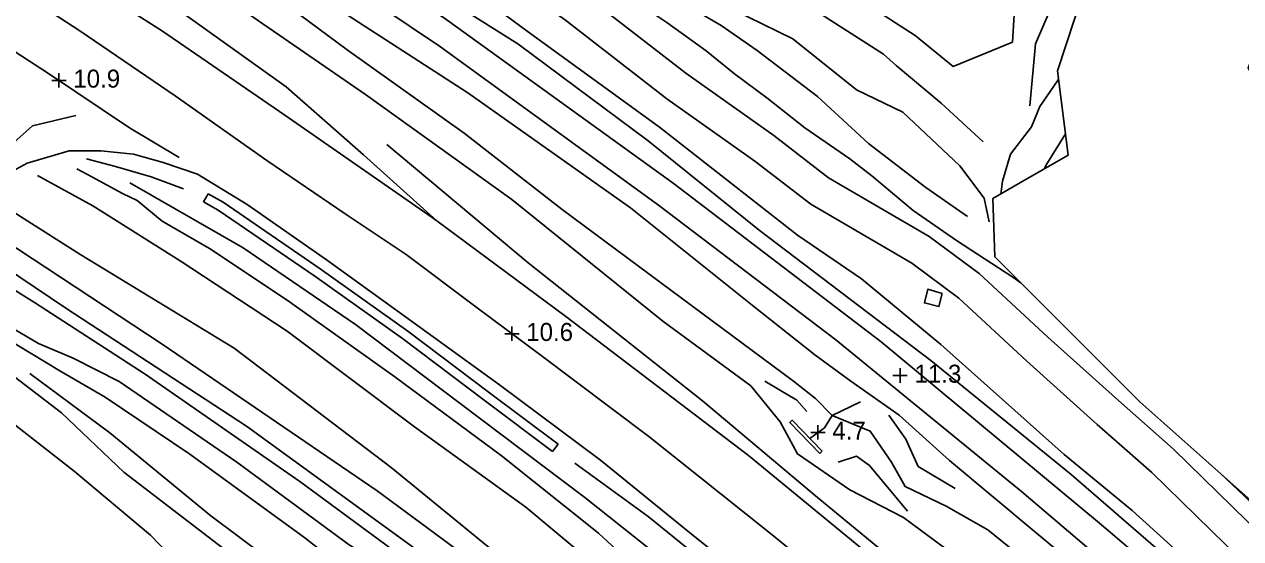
# Model space of a CAD drawing. Extents: x 2316231 to 2323598, y 363169 to 371906.
# Drawn here: x 2320501.8 to 2320840, y 365756.1 to 365899 of the extents above; entities that cross this region are included whole.
import ezdxf

# ---------------------------------------------------------------- set-up
doc = ezdxf.new("R2010")
doc.units = 0
for name, color, linetype in [('RD_DTM_BkLn1', 7, 'Continuous'), ('RD_DTM_Holes', 7, 'Continuous'), ('RD_DTM_Void', 7, 'Continuous'), ('RD_EX_H2O', 7, 'Continuous'), ('RD_EX_Road', 7, 'Continuous')]:
    doc.layers.add(name, color=color, linetype=linetype)

msp = doc.modelspace()

# ---------------------------------------------------------------- linework, layer by layer
at = {"layer": 'RD_DTM_BkLn1'}
msp.add_line((2320531.022, 365870.231), (2320544.889, 365862.035), dxfattribs=at)
for points in [[(2320183.14, 366148.693), (2320239.09, 366117.639), (2320296.494, 366085.739), (2320349.802, 366055.132), (2320405.378, 366025.418), (2320448.083, 365999.362), (2320490.768, 365974.618), (2320559.324, 365931.873), (2320617.279, 365892.959), (2320678.148, 365848.809), (2320727.47, 365811.314), (2320779.04, 365769.194), (2320836.996, 365719.869), (2320889.686, 365671.382)], [(2320125.425, 366145.994), (2320161.294, 366129.015), (2320184.806, 366118.194), (2320219.268, 366097.334), (2320257.75, 366078.61), (2320301.401, 366053.593), (2320339.6, 366032.049), (2320388.854, 366006.136), (2320433.491, 365980.54), (2320471.094, 365961.437), (2320509.936, 365935.57), (2320558.33, 365906.04), (2320596.656, 365879.53), (2320637.36, 365850.344), (2320679.307, 365816.521), (2320703.841, 365798.525), (2320711.978, 365788.521), (2320716.795, 365779.622), (2320731.36, 365769.609), (2320746.226, 365761.92), (2320773.664, 365741.714), (2320802.121, 365716.946), (2320848.849, 365676.056), (2320875.469, 365654.227)], [(2320182.737, 366143.817), (2320231.045, 366116.001), (2320278.866, 366087.979), (2320328.405, 366059.321), (2320373.611, 366034.853), (2320417.281, 366010.392), (2320460.243, 365986.01), (2320498.805, 365963.232), (2320547.113, 365932.568), (2320590.276, 365902.488), (2320625.131, 365879.992), (2320670.35, 365847.996), (2320704.214, 365820.962), (2320721.604, 365807.145), (2320731.665, 365799.894), (2320745.055, 365790.38), (2320759.08, 365777.797), (2320794.333, 365748.347), (2320828.782, 365718.919), (2320859.537, 365690.73), (2320885.477, 365666.303)], [(2320232.419, 366129.527), (2320276.765, 366104.361), (2320326.97, 366076.072), (2320377.845, 366047.504), (2320438.873, 366013.35), (2320491.432, 365981.475), (2320553.439, 365943.338), (2320618.359, 365900.899), (2320682.218, 365854.928), (2320740.085, 365810.827), (2320800.745, 365760.357), (2320857.803, 365711.976), (2320894.516, 365677.21)], [(2320320.221, 366098.87), (2320343.73, 366084.834), (2320356.505, 366077.219), (2320384.555, 366059.676), (2320419.447, 366040.181), (2320447.866, 366021.901), (2320471.868, 366008.615), (2320488.936, 365996.515), (2320514.303, 365982.74), (2320529.316, 365972.626), (2320554.954, 365955.917), (2320587.739, 365935.149), (2320612.576, 365918.662), (2320641.664, 365897.147), (2320678.381, 365870.456), (2320716.77, 365840.459), (2320734.571, 365828.326), (2320756.632, 365810.066), (2320790.938, 365779.493), (2320809.818, 365763.92), (2320848.173, 365729.232), (2320863.138, 365716.2), (2320899.36, 365685.757), (2320900.62, 365684.576)], [(2320315.308, 366088.614), (2320345.863, 366070.993), (2320387.782, 366047.357), (2320430.265, 366024.388), (2320470.415, 366003.883), (2320504.878, 365981.214), (2320529.854, 365965.458), (2320578.485, 365933.231), (2320618.03, 365906.824), (2320639.032, 365893.635), (2320675.308, 365866.642), (2320706.175, 365841.844), (2320753.882, 365805.574), (2320792.936, 365773.891), (2320828.235, 365743.377), (2320879.989, 365695.168), (2320896.418, 365679.505)], [(2320768.392, 365866.361), (2320756.708, 365877.083), (2320744.252, 365887.566), (2320740.687, 365890.766), (2320726.055, 365900.142), (2320710.288, 365910.418), (2320684.057, 365924.05), (2320656.815, 365943.875), (2320639.525, 365956.203), (2320622.508, 365966.719), (2320606.645, 365977.824), (2320598.246, 365982.88), (2320591.282, 365990.258), (2320583.747, 365995.374), (2320568.719, 366003.277), (2320549.326, 366013.752), (2320528.668, 366027.008), (2320512.279, 366039.596), (2320486.864, 366058.051)], [(2320499.898, 366035.117), (2320518.783, 366024.708), (2320539.775, 366013.575), (2320551, 366005.825), (2320566.423, 365997.349), (2320574.595, 365991.103), (2320579.668, 365988.57), (2320584.457, 365982.129), (2320591.38, 365978.131), (2320601.704, 365971.102), (2320609.064, 365967.122), (2320630.418, 365948.02), (2320645.146, 365939.719), (2320660.769, 365929.255), (2320670.56, 365922.043), (2320694.612, 365905.223), (2320715.486, 365895.037), (2320733.213, 365880.79), (2320746.065, 365874.627), (2320761.94, 365859.741), (2320768.707, 365850.734), (2320770.054, 365844.1)], [(2320764.035, 365845.663), (2320752.506, 365853.724), (2320736.562, 365865.941), (2320722.342, 365878.987), (2320705.589, 365891.721), (2320695.572, 365898.724), (2320680.484, 365907.597), (2320662.741, 365921.455), (2320651.647, 365927.407), (2320628.585, 365944.084), (2320610.724, 365955.154), (2320600.628, 365963.434), (2320580.454, 365977.629), (2320563.696, 365987.078), (2320549.277, 365995.494), (2320537.141, 366003.22), (2320521.388, 366014.595), (2320497.7, 366028.456)], [(2320778.851, 365827.229), (2320776.707, 365828.796), (2320760.961, 365838.918), (2320748.976, 365847.328), (2320737.491, 365856.96), (2320731.391, 365861.609), (2320718.843, 365870.309), (2320708.251, 365878.642), (2320699.269, 365885.241), (2320691.419, 365891.649), (2320680.432, 365899.55), (2320665.759, 365909.434), (2320648.973, 365921.401), (2320634.153, 365930.933), (2320610.18, 365947.515), (2320596.411, 365956.939), (2320573.742, 365971.933), (2320553.973, 365984.422), (2320539.048, 365994.014), (2320520.799, 366003.328), (2320499.315, 366016.701)], [(2320531.022, 365870.231), (2320508.52, 365885.4), (2320485.858, 365899.969), (2320466.913, 365913.192), (2320446.479, 365926.41), (2320433.746, 365934.556)], [(2320543.695, 365879.161), (2320517.247, 365897.216), (2320496.287, 365910.936), (2320471.832, 365924.913)], [(2320800.011, 365919.344), (2320788.86, 365907.244), (2320783.018, 365893.597), (2320781.363, 365876.411)], [(2320789.378, 365883.84), (2320789.071, 365883.323), (2320784.137, 365876.199), (2320781.833, 365870.52), (2320776.044, 365862.969), (2320773.799, 365855.457), (2320773.336, 365851.874)], [(2320855.357, 365629.958), (2320845.868, 365638.904), (2320819.287, 365663.389), (2320796.672, 365683.748), (2320768.394, 365708.644), (2320741.53, 365731.29), (2320709.31, 365757.523), (2320675.444, 365784.438), (2320645.131, 365807.256), (2320627.321, 365820.5), (2320607.968, 365835.099), (2320591.031, 365846.394), (2320569.199, 365861.189), (2320543.695, 365879.161)], [(2320516.092, 365873.737), (2320504.049, 365870.79), (2320492.709, 365860.72), (2320483.032, 365850.358), (2320472.873, 365837.355)], [(2320602.629, 365865.677), (2320641.904, 365832.75), (2320690.389, 365794.379), (2320722.377, 365767.546), (2320771.111, 365727.387), (2320832.413, 365675.302), (2320868.558, 365645.887)], [(2320546.046, 365853.297), (2320537.071, 365856.611), (2320527.144, 365859.511), (2320519.123, 365861.643)], [(2320505.475, 365856.979), (2320520.864, 365848.587), (2320545.172, 365833.324), (2320574.899, 365813.74), (2320610.258, 365787.16), (2320641.215, 365764.842), (2320658.117, 365750.723), (2320662.317, 365742.611), (2320663.086, 365735.015), (2320670.708, 365727.381), (2320681.36, 365723.951), (2320702.529, 365710.89), (2320738.215, 365682.049), (2320755.731, 365664.117), (2320790.277, 365635.787), (2320826.19, 365604.332), (2320830.311, 365599.735)], [(2320531.154, 365854.994), (2320562.66, 365836.912), (2320593.866, 365815.631), (2320622.996, 365793.667), (2320657.616, 365767.534), (2320674.76, 365753.896), (2320691.644, 365742.188), (2320712.309, 365725.73), (2320742.067, 365699.137), (2320765.35, 365677.399), (2320794.487, 365652.244), (2320830.03, 365620.462), (2320839.699, 365611.064)], [(2320494.756, 365849.313), (2320517.539, 365834.967), (2320560.151, 365809.006), (2320603.795, 365775.848), (2320645.456, 365741.875), (2320664.804, 365725.847), (2320689.325, 365706.764), (2320719.517, 365681.82), (2320774.711, 365633.699), (2320816.181, 365591.988), (2320820.585, 365587.999)], [(2320487.964, 365837.237), (2320513.325, 365820.129), (2320563.533, 365787.35), (2320615.078, 365749.886), (2320667.434, 365710.191), (2320715.063, 365670.543), (2320756.33, 365633.36), (2320801.65, 365593.339), (2320814.522, 365580.683)], [(2320495.801, 365839.314), (2320540.146, 365810.177), (2320599.875, 365769.409), (2320648.098, 365733.83), (2320703.015, 365690.061), (2320756.957, 365642.96), (2320808.871, 365595.211), (2320818.714, 365585.741)], [(2320485.487, 365833.622), (2320504.647, 365821.714), (2320535.41, 365801.833), (2320578.386, 365771.968), (2320617.431, 365743.287), (2320659.726, 365709.98), (2320694.071, 365682.621), (2320730.364, 365652.213), (2320749.321, 365632.325), (2320781.055, 365603.107), (2320810.117, 365575.367)], [(2320475.372, 365817.646), (2320481.696, 365821.632), (2320490.565, 365819.23), (2320505.711, 365810.344), (2320515.374, 365806.23), (2320528.128, 365799.749), (2320560.904, 365777.338), (2320592.16, 365754.331), (2320614.238, 365740.301), (2320637.32, 365721.378), (2320642.869, 365714.337), (2320644.444, 365714.613)], [(2320434.813, 365750.977), (2320450.725, 365774.25), (2320465.315, 365792.894), (2320477.836, 365808.657), (2320485.329, 365810.561), (2320491.873, 365806.533), (2320512.09, 365791.073), (2320529.506, 365774.584), (2320568.018, 365744.987)], [(2320503.28, 365801.995), (2320525.612, 365785.54), (2320553.699, 365762.395), (2320584.774, 365739.166), (2320608.674, 365720.434), (2320622.584, 365709.046), (2320627.658, 365704.681), (2320620.473, 365687.552), (2320621.449, 365684.302)], [(2320719.4, 365791.407), (2320716.485, 365794.634), (2320714.996, 365795.539), (2320707.711, 365799.884)], [(2320742.218, 365790.368), (2320746.923, 365783.774), (2320750.303, 365776.169), (2320760.614, 365769.99)], [(2320654.91, 365777.105), (2320675.289, 365762.269), (2320700.245, 365742.034), (2320733.027, 365713.442)], [(2320728.136, 365777.366), (2320733.178, 365778.969), (2320736.786, 365776.384), (2320747.348, 365763.726)], [(2320891.97, 365722.614), (2320872.135, 365739.369), (2320854.837, 365753.86), (2320840.972, 365767.941), (2320834.306, 365774.288)]]:
    msp.add_lwpolyline(points, dxfattribs=at)
at = {"layer": 'RD_DTM_Holes'}
msp.add_lwpolyline([(2320869.591, 365742.934), (2320812.024, 365794.086), (2320771.624, 365834.449), (2320771.151, 365850.598), (2320778.817, 365855.076), (2320792.1, 365862.675), (2320789.082, 365886.135), (2320803.561, 365930.13), (2320827.143, 365964.83), (2320847.36, 365988.415), (2320856.368, 365987.689), (2320864.974, 365979.309), (2320883.365, 365970.076), (2320884.869, 365948.36), (2320851.417, 365908.749), (2320842.106, 365886.919), (2320849.793, 365872.134), (2320872.565, 365844.447), (2320903.42, 365831.029), (2320938.866, 365827.634), (2320967.2, 365821.516), (2320982.278, 365798.58), (2320978.958, 365776.734), (2320986.815, 365765.174)], dxfattribs=at)
at = {"layer": 'RD_DTM_Void'}
for p, q in [((2320511.419, 365881.446), (2320511.419, 365885.446)), ((2320509.419, 365883.446), (2320513.419, 365883.446)), ((2320637.367, 365811.03), (2320637.367, 365815.03)), ((2320635.367, 365813.03), (2320639.367, 365813.03)), ((2320745.333, 365799.432), (2320745.333, 365803.432)), ((2320743.333, 365801.432), (2320747.333, 365801.432)), ((2320722.479, 365783.613), (2320722.479, 365787.613)), ((2320720.479, 365785.613), (2320724.479, 365785.613))]:
    msp.add_line(p, q, dxfattribs=at)
at = {"layer": 'RD_EX_H2O'}
msp.add_line((2320734.346, 365794.154), (2320726.404, 365790.317), dxfattribs=at)
for points in [[(2320221.567, 366109.612), (2320246.01, 366095.432), (2320275.628, 366082.36), (2320308.416, 366062.762), (2320348.828, 366042.465), (2320390.844, 366019.006), (2320428.93, 365996.954), (2320463.386, 365976.566), (2320497.874, 365954.051), (2320534.331, 365932.126), (2320567.896, 365909.551), (2320591.597, 365891.98), (2320624.103, 365868.768), (2320651.363, 365847.548), (2320681.527, 365825.11), (2320715.721, 365799.88), (2320721.819, 365795.078), (2320726.404, 365790.317)], [(2320791.336, 365868.616), (2320785.882, 365859.8), (2320785.441, 365858.865)], [(2320516.418, 365858.9), (2320520.609, 365856.673), (2320529.119, 365851.994), (2320533.137, 365850.113), (2320540.156, 365844.329), (2320553.262, 365836.686), (2320574.84, 365822.379), (2320604.794, 365801.078), (2320634.374, 365779.238), (2320661.487, 365757.618), (2320671.313, 365748.515), (2320681.202, 365738.547)], [(2320404.421, 365703.635), (2320417.803, 365731.607), (2320433.671, 365757.03), (2320449.595, 365781.283), (2320465.031, 365801.466), (2320472.758, 365810.812), (2320479.737, 365815.157), (2320484.217, 365819.072), (2320489.885, 365815.823), (2320499.751, 365809.969), (2320511.62, 365802.684), (2320524.233, 365795.389), (2320547.79, 365779.545), (2320579.835, 365756.292), (2320626.977, 365719.296), (2320640.945, 365703.207)], [(2320726.404, 365790.317), (2320724.258, 365786.929), (2320720.221, 365783.942)], [(2320881.233, 365661.182), (2320857.755, 365681.643), (2320823.997, 365711.57), (2320791.11, 365741.192), (2320769.711, 365758.569), (2320758.117, 365765.095), (2320746.733, 365770.566), (2320742.906, 365777.385), (2320737.033, 365785.978), (2320726.404, 365790.317)]]:
    msp.add_lwpolyline(points, dxfattribs=at)
at = {"layer": 'RD_EX_Road'}
for p, q in [((2320552.901, 365851.922), (2320551.657, 365849.719)), ((2320650.204, 365782.332), (2320648.684, 365780.309))]:
    msp.add_line(p, q, dxfattribs=at)
for points in [[(2320323.899, 366113.021), (2320353.981, 366094.621), (2320381.93, 366078.827), (2320411.483, 366061.572), (2320429.335, 366050.162), (2320458.032, 366033.49), (2320473.353, 366024.244), (2320495.209, 366011.149), (2320520.435, 365996.933), (2320537.434, 365986.383), (2320550.651, 365978.213), (2320571.299, 365965.571), (2320597.468, 365949.743), (2320625.215, 365930.292), (2320657.566, 365907.315), (2320685.711, 365885.437), (2320710.189, 365868.145), (2320725.44, 365856.384), (2320753.441, 365840.046), (2320767.348, 365829.779), (2320786.407, 365812.075), (2320806.036, 365794.449), (2320821.311, 365780.953), (2320846.032, 365756.88)], [(2320319.14, 366105.537), (2320349.484, 366086.977), (2320377.513, 366071.138), (2320406.858, 366054.005), (2320424.718, 366042.589), (2320453.513, 366025.86), (2320468.783, 366016.645), (2320490.753, 366003.481), (2320515.919, 365989.3), (2320532.765, 365978.844), (2320546.005, 365970.66), (2320566.689, 365957.996), (2320592.623, 365942.31), (2320620.103, 365923.046), (2320652.275, 365900.197), (2320680.429, 365878.312), (2320704.921, 365861.009), (2320720.478, 365849.013), (2320748.559, 365832.628), (2320761.68, 365822.942), (2320780.427, 365805.528), (2320800.138, 365787.827), (2320815.279, 365774.45), (2320839.973, 365750.403)], [(2320416.682, 365973.734), (2320444.212, 365959.893), (2320470.233, 365946.476), (2320495.474, 365933.979), (2320518.139, 365920.533), (2320544.115, 365903.453), (2320574.558, 365881.626), (2320596.127, 365862.734), (2320616.537, 365844.377)], [(2320416.682, 365973.734), (2320422.387, 365970.576), (2320458.77, 365949.337), (2320500.672, 365922.44), (2320540.243, 365897.179), (2320574.201, 365873.831), (2320615.174, 365845.386), (2320616.537, 365844.377)], [(2320777.359, 365906.278), (2320776.546, 365894.104), (2320760.118, 365887.335), (2320749.542, 365895.964), (2320735.672, 365904.81)], [(2320715.128, 365734.985), (2320686.801, 365757.814), (2320661.973, 365777.858), (2320633.918, 365798.792), (2320611.114, 365815.36), (2320586.143, 365833.385), (2320563.777, 365849.002), (2320549.913, 365857.411), (2320540.44, 365860.648), (2320532.138, 365862.996), (2320523.108, 365863.877), (2320514.221, 365863.857), (2320502.609, 365860.408), (2320494.34, 365855.961), (2320488.202, 365849.845), (2320476.454, 365836.424), (2320457.11, 365809.897), (2320436.419, 365781.508), (2320409.579, 365738.447)], [(2320650.204, 365782.332), (2320631.178, 365796.631), (2320608.462, 365813.728), (2320584.015, 365831.088), (2320557.057, 365849.575), (2320552.901, 365851.922)], [(2320648.684, 365780.309), (2320629.657, 365794.608), (2320606.968, 365811.684), (2320582.566, 365829.012), (2320555.716, 365847.426), (2320551.657, 365849.719)], [(2320616.537, 365844.377), (2320652.389, 365817.861), (2320703.175, 365779.237), (2320743.767, 365745.857), (2320803.456, 365695.174), (2320850.363, 365653.116)], [(2320757.056, 365824.23), (2320756.125, 365820.602), (2320752.108, 365821.621), (2320753.065, 365825.461), (2320757.056, 365824.23)], [(2320442.434, 365749.999), (2320457.428, 365772.668), (2320472.17, 365792.161), (2320479.57, 365799.018), (2320491.405, 365793.719), (2320515.61, 365774.865), (2320536.896, 365757.016), (2320551.808, 365741.61)], [(2320723.645, 365780.366), (2320723, 365779.783), (2320714.621, 365788.36), (2320715.314, 365789.013), (2320723.645, 365780.366)]]:
    msp.add_lwpolyline(points, dxfattribs=at)

# ---------------------------------------------------------------- texts
at = {"layer": 'RD_DTM_Void'}
for s, p in [('10.9', (2320515.419, 365881.446)), ('10.6', (2320641.367, 365811.03)), ('11.3', (2320749.333, 365799.432)), ('4.7', (2320726.479, 365783.613))]:
    msp.add_text(s, height=5, dxfattribs=at).set_placement(p)

doc.saveas('drawing.dxf')
